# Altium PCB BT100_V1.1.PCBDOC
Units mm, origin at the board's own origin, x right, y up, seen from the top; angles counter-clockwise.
Board outline 126.04 x 85.33 mm, 4 copper layers (Top Layer, GND, POWER, Bottom Layer); 82 components, 62 nets, 257 pads, 145 vias.
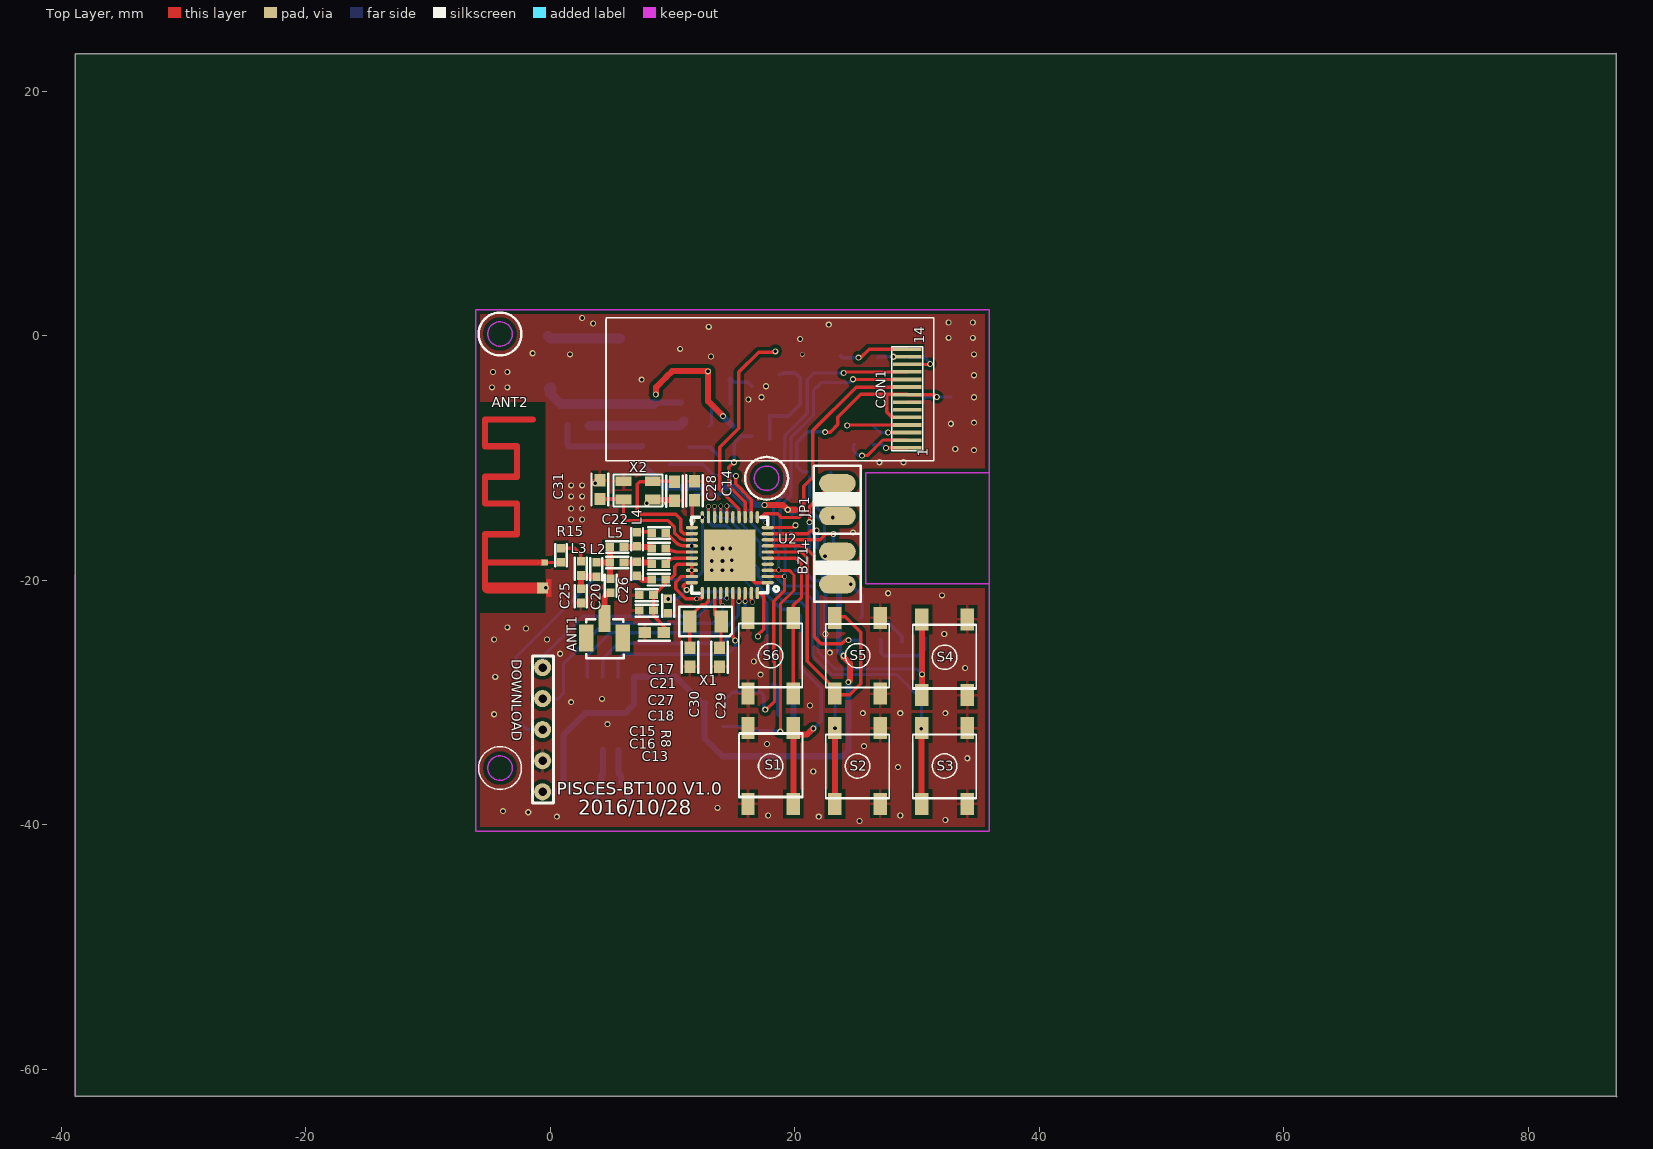
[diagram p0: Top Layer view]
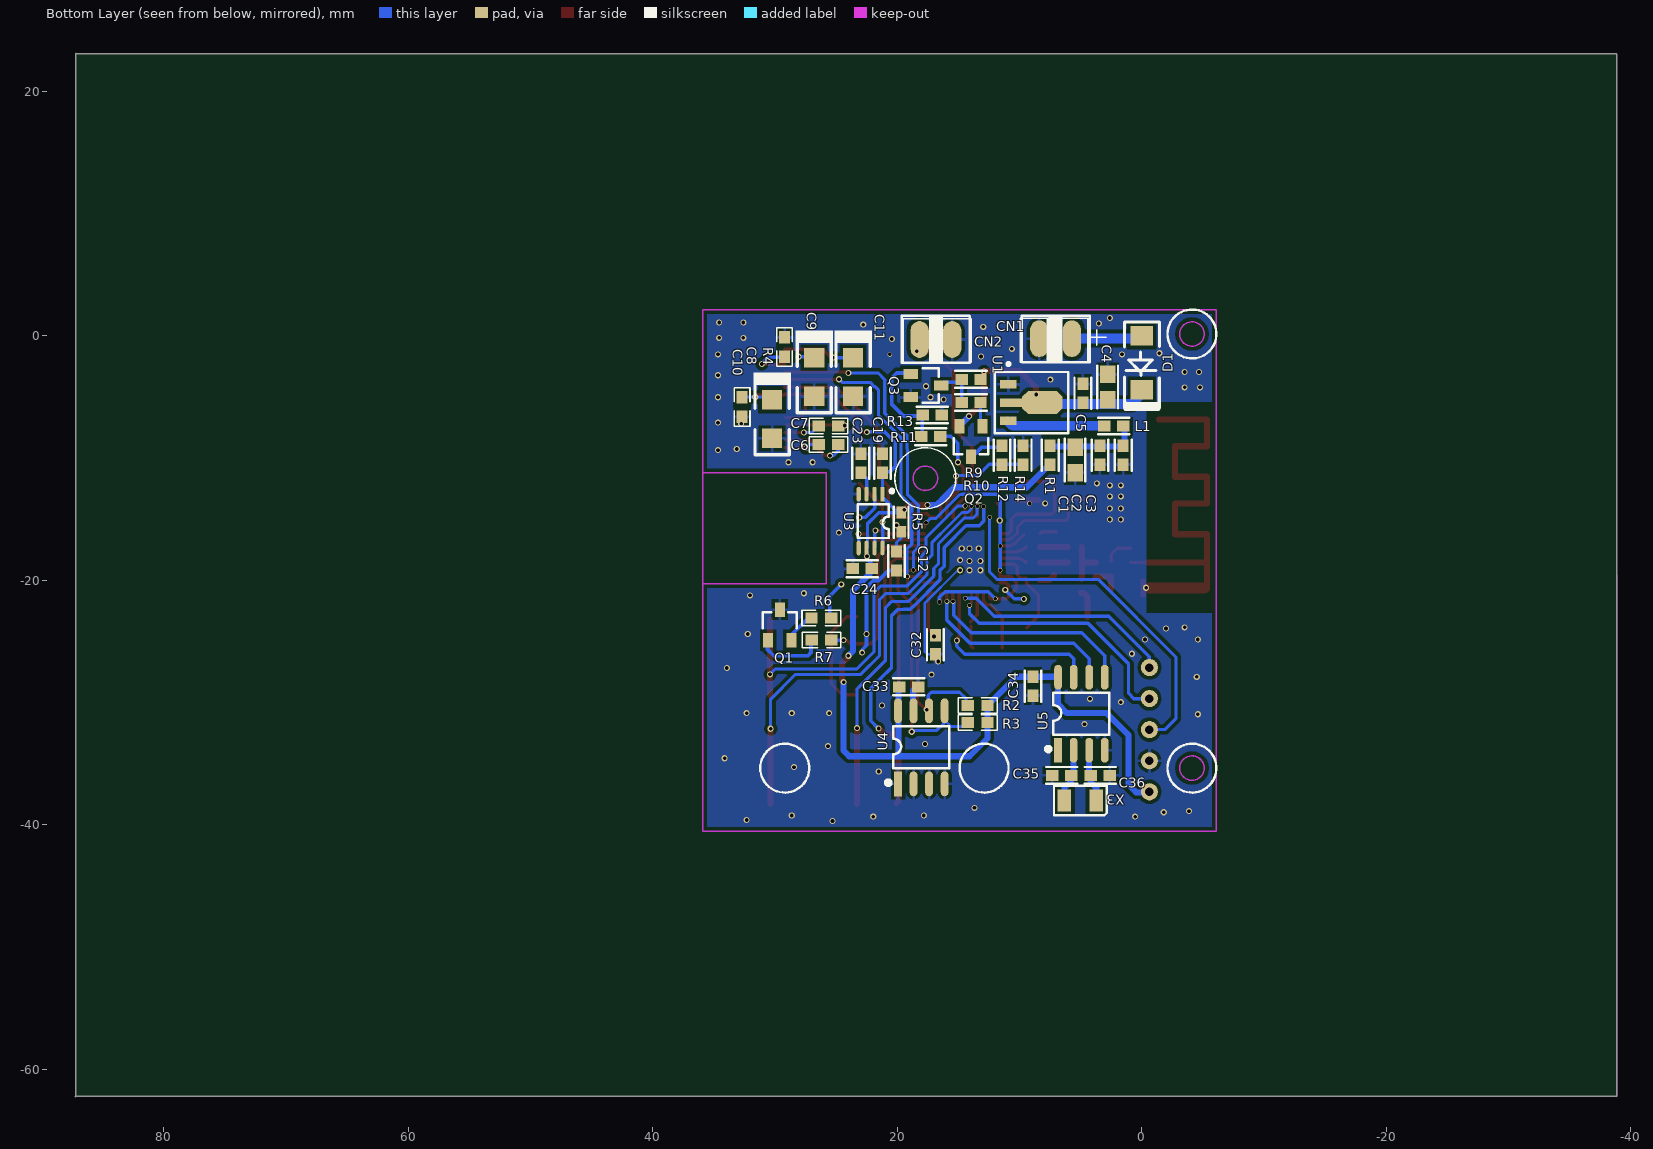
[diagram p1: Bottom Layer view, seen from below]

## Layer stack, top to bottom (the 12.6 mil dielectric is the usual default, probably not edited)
Top Solder: solder mask 0.0102, Solder Resist, Dk 3.5
Top Layer: signal copper 0.0356
Dielectric1: core 0.32, FR-4, Dk 4.8
GND: signal copper 0.0356
Dielectric2: prepreg 0.32, FR-4, Dk 4.8
POWER: signal copper 0.0356
Dielectric3: core 0.32, FR-4, Dk 4.8
Bottom Layer: signal copper 0.0356
Bottom Solder: solder mask 0.0102, Solder Resist, Dk 3.5

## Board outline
-38.826,-62.183 -38.826,23.037 87.104,23.037 87.154,23.087 87.174,23.067 87.174,9.757 87.174,-62.213 87.204,-62.243 87.164,-62.203 -38.836,-62.203

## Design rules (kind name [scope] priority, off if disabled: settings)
Clearance [All] p1: gap=0.1
ComponentClearance [All] p1 off: gap=0.254 collisioncheckmode=3 verticalgap=0.254 showdistances=FALSE
FabricationTestPointUsage TestPointUsage [All] p1: valid=0 allowmultiple=FALSE
FabricationTestpoint Testpoint [(IsPad And (OnTopLayer Or OnBottomLayer))] p1: side=3 testpointundercomponent=TRUE minsize=1.016 maxsize=2.54 preferedsize=1.524 minholesize=0 maxholesize=1.016 preferedholesize=0.813 testpointgrid=0.025 allowsidetop=TRUE allowsidebottom=TRUE usegrid=TRUE gridtolerance=0
Height [All] p1 off: minheight=0 maxheight=25.4 prefheight=12.7
PolygonConnect PolygonConnect_1 [IsVia] p1: connectstyle=Direct reliefconductorwidth=0.254 reliefentries=4 polygonreliefangle="90 Angle" airgapwidth=0.254
PolygonConnect [All] p2: connectstyle=Relief reliefconductorwidth=0.254 reliefentries=4 polygonreliefangle="90 Angle" airgapwidth=0.254
RoutingVias [All] p1: holewidth=0.4 width=0.7 viastyle="Through Hole" minholewidth=0.2 minwidth=0.2 maxholewidth=0.711 maxwidth=1.27
SolderMaskExpansion [All] p1: expansion=0.102
UnpouredPolygon [All] p1: allowunpoured=FALSE
Width [All] p1: maxlimit=1 minlimit=0.2 preferedwidth=0.28 midlayer1_minwidth=0.254 midlayer1_maxwidth=0.254 midlayer1_prefwidth=0.254 midlayer2_minwidth=0.254 midlayer2_maxwidth=0.254 midlayer2_prefwidth=0.254 minimp=50.000000 maximp=50.000000 favimp=50.000000
25 further rules are at their usual default settings.

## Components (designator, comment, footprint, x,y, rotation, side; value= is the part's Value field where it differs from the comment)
ANT1 "ANT" IPEX 4.435,-23.124 r90 top
ANT2 "ANT" ANT -0.45,-18.54 r90 top
BZ1 "BUZZER" 2PAD-9 23.485,-17.663 r270 top
C1 "10uf/10V,0805" PC5-*****-**-0A_0805_TDK 5.451,-10.17 r90 bottom
C2 "0.1uf" PC5-*****-**-0A_0603_TDK 3.419,-9.789 r90 bottom
C3 "2.2uf" PC5-*****-**-0A_0603_TDK 1.514,-9.789 r270 bottom
C4 "10uf/10V,0805" PC5-*****-**-0A_0805_TDK 2.784,-4.201 r270 bottom
C5 "0.1uf" PC5-*****-**-0A_0603_TDK 4.816,-4.709 r270 bottom
C6 "1UF" 0603 26.406,-8.9 r180 bottom
C7 "1UF" 0603 26.406,-7.376 r180 bottom
C8 "4.7UF" 3216C 30.236,-5.217 r90 bottom
C9 "4.7uf" 3216C 26.787,-1.788 r90 bottom
C10 "1uf" 0603 32.664,-5.043 r270 bottom
C11 "4.7uF" 3216C 23.612,-1.788 r90 bottom
C12 "1uf" PC5-*****-**-0A_0603_TDK 20.056,-18.425 r270 bottom
C13 "0.1uf" PC7-*****-KO-0A_0603_TDK 8.499,-24.267 r180 top
C14 "0.1uf" PC5-*****-**-0A_0603_TDK 11.79,-12.69 r90 top
C15 "0.1uf" PC7-*****-KQA0A_0402_YAGEO 7.864,-21.219 r180 top
C16 "0.1uf" PC7-*****-KQA0A_0402_YAGEO 7.864,-22.489 r180 top
C17 "0.1uf" PC7-*****-KQA0A_0402_YAGEO 8.88,-16.139 r180 top
C18 "220pf" PC7-*****-KQA0A_0402_YAGEO 8.88,-19.949 r0 top
C19 "1uf" PC5-*****-**-0A_0603_TDK 21.199,-10.424 r270 bottom
C20 "20P" PC7-*****-KQA0A_0402_YAGEO 4.943,-20.457 r270 top
C21 "18p" PC7-*****-KQA0A_0402_YAGEO 8.88,-17.409 r180 top
C22 "1p" PC7-*****-KQA0A_0402_YAGEO 5.451,-17.282 r180 top
C23 "1uf" PC5-*****-**-0A_0603_TDK 22.977,-10.424 r270 bottom
C24 "0.1uf" PC5-*****-**-0A_0603_TDK 22.85,-19.06 r180 bottom
C25 "1p" PC7-*****-KQA0A_0402_YAGEO 2.504,-21.283 r90 top
C26 "1p" PC7-*****-KQA0A_0402_YAGEO 7.102,-19.06 r270 top
C27 "18p" PC7-*****-KQA0A_0402_YAGEO 8.88,-18.679 r180 top
C28 "27p" PC7-*****-KO-0A_0603_TDK 10.15,-12.71 r90 top
C29 "15P" PC5-*****-**-0A_0603_TDK 13.833,-26.299 r90 top
C30 "15P" PC7-*****-KO-0A_0603_TDK 11.42,-26.299 r90 top
C31 "27p" PC7-*****-KO-0A_0603_TDK 4.054,-12.583 r270 top
C32 "1uf" PC5-*****-**-0A_0603_TDK 16.881,-25.283 r90 bottom
C33 "0.1uf" PC5-*****-**-0A_0603_TDK 19.04,-28.712 r0 bottom
C34 "0.1uf" PC7-*****-KO-0A_0603_TDK 8.894,-28.663 r270 bottom
C35 "15P" PC7-*****-KO-0A_0603_TDK 6.554,-35.953 r0 bottom
C36 "15P" PC7-*****-KO-0A_0603_TDK 3.404,-35.953 r180 bottom
CN1 "CN1" 2PAD-9 5.714,-0.243 r0 bottom
CN2 "CN1" 2PAD-9 18.164,-0.313 r180 bottom
CON1 "FPC-14PIN-F" FFC6214 29.2,-9.154 r90 top locked
D1 "SS12" SS12-DIDEO -0.01,-0.01 r270 bottom
DOWNLOAD "debugger" ISCP-5PIN -0.63,-32.22 r90 top (schematic designator JP2)
JP1 "SIP2" 2PAD-9 23.485,-14.742 r90 top
L1 "BLM18HG102SN1" PC5-*****-**-0A_0603_TDK 2.276,-7.376 r180 bottom
L2 "1nH" PC5-*****-**-0A_0402_TDK 3.764,-19.123 r270 top
L3 "3nH" PC5-*****-**-0A_0402_TDK 2.504,-19.033 r90 top
L4 "2nH" PC5-*****-**-0A_0402_TDK 7.102,-16.647 r270 top
L5 "2nH" PC5-*****-**-0A_0402_TDK 5.451,-18.552 r180 top
Q1 "BC857C" PTR-C0025-00-2A_2SC1623 29.594,-23.653 r180 bottom
Q2 "BC857B" PTR-C0025-00-2A_2SC1623 13.96,-8.646 r0 bottom
Q3 "BC847B" PTR-C0025-00-2A_2SC1623 17.643,-4.074 r270 bottom
R1 "0ohm" PC5-*****-**-0A_0603_TDK 7.483,-9.789 r270 bottom
R2 "4.7K" 0603 14.214,-30.236 r180 bottom
R3 "4.7K" 0603 14.214,-31.633 r180 bottom
R4 "390K" 0603 29.2,-0.137 r270 bottom
R5 "0ohm" PRC-*****-AM-0A_0603 19.675,-15.25 r90 bottom
R6 "10Ω" 0603 26.99,-23.073 r180 bottom
R7 "1K" 0603 25.39,-24.902 r0 bottom
R8 "56k" PRC-*****-BM-0A_0402 9.642,-22.108 r270 top
R9 "47K" PC7-*****-KO-0A_0603_TDK 13.96,-3.566 r180 bottom
R10 "30K" PC5-*****-**-0A_0603_TDK 13.96,-5.471 r180 bottom
R11 "4.7K" PC5-*****-**-0A_0603_TDK 17.262,-8.265 r0 bottom
R12 "75K" PC5-*****-**-0A_0603_TDK 11.42,-9.789 r90 bottom
R13 "100K" PC5-*****-**-0A_0603_TDK 17.135,-6.487 r0 bottom
R14 "30K" PC5-*****-**-0A_0603_TDK 9.694,-9.783 r270 bottom
R15 "0ohm" PC7-*****-KQA0A_0402_YAGEO 0.884,-17.953 r90 top
S1 "SW-PB" TS-030 18.024,-35.189 r270 top
S2 "SW-PB" TS-030 25.136,-35.189 r90 top
S3 "SW-PB" TS-030 32.248,-35.189 r90 top
S4 "SW-PB" TS-030 32.248,-26.299 r90 top
S5 "SW-PB" TS-030 25.136,-26.172 r90 top
S6 "SW-PB" TS-030 18.024,-26.172 r90 top
U1 "HT7333" SOT89 9.515,-5.471 r270 bottom
U2 "CC2541" CC2530_QFN40 17.77,-20.203 r180 top
U3 "PT5102" PT5102 21.199,-12.964 r270 bottom
U4 "AT24C64N" PIC-00570-40-2A_93LC46B 18.024,-33.665 r90 bottom
U5 "DS1302Z" PIC-00570-40-2A_93LC46B 4.934,-30.913 r90 bottom
X1 "32.768KHZ,F=12.5P" FC-135 12.69,-23.378 r180 top
X2 "CY_3225" CY_3225 6.086,-12.329 r0 top
X3 "32.768KHZ,F=6P" FC-135 5.024,-38.023 r0 bottom

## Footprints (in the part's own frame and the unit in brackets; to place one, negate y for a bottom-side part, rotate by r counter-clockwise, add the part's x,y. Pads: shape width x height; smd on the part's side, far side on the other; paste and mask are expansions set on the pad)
2PAD-9 [mm]
  oval 1.5x3 smd: 1(0,0) 2(2.667,0)
  silkscreen extent -1.47,-1.89 4.09,1.92
0603 [mm]
  rect 1x0.9 smd: 1(-0.005,-0.007) 2(1.595,-0.007)
  silkscreen extent -0.79,-0.64 2.38,0.63
3216C [mm]
  rect 1.6x1.65 smd: 1(-0.009,-0.005) 2(-3.184,-0.005)
  silkscreen extent -4.52,-1.54 2.21,1.52
ANT [mm]
  rect 0.5x0.5 smd: 1(0,0)
  rect 0.9x0.9 smd: 2(-2.1,0.2)
  Top Layer lines w0.5: -2.26,4.79 -2.21,4.84 -2.15,4.9 0,4.9 ; 11.7,0.96 11.7,4.9 9.5,4.9 9.5,2.26 7,2.26 7,4.9 4.8,4.9 4.8,2.26 2.3,2.26 2.3,4.9 0,4.9 ; 0,0 0,4.9
  Top Layer lines w0.9: -2.1,4.65 -2.1,0.2
CC2530_QFN40 [mm]
  oval 1x0.28 smd: 1(-0.011,-0.009) 2(-0.011,-0.509) 3(-0.011,-1.009) 4(-0.011,-1.509) 5(-0.011,-2.009) 6(-0.011,-2.509) 7(-0.011,-3.009) 8(-0.011,-3.509) 9(-0.011,-4.009) 10(-0.011,-4.509) 21(6.189,-4.509) 22(6.189,-4.009) 23(6.189,-3.509) 24(6.189,-3.009) 25(6.189,-2.509) 26(6.189,-2.009) 27(6.189,-1.509) 28(6.189,-1.009) 29(6.189,-0.509) 30(6.189,-0.009)
  oval 0.28x1 smd: 11(0.832,-5.359) 12(1.332,-5.359) 13(1.832,-5.359) 14(2.332,-5.359) 15(2.832,-5.359) 16(3.332,-5.359) 17(3.832,-5.359) 18(4.332,-5.359) 19(4.832,-5.359) 20(5.332,-5.359) 31(5.332,0.841) 32(4.832,0.841) 33(4.332,0.841) 34(3.832,0.841) 35(3.332,0.841) 36(2.832,0.841) 37(2.332,0.841) 38(1.832,0.841) 39(1.332,0.841) 40(0.832,0.841)
  rect 4.2x4.2 smd: 41(3.089,-2.259)
  silkscreen extent -0.91,-5.37 6.21,0.85
CY_3225 [mm]
  round 0.5 on Top Overlay: 0(-0.64,-2.06)
  rect 1.3x0.8 smd: 1(-0.095,-1.07) 2(2.293,-1.07) 3(2.293,0.428) 4(-0.095,0.428)
  silkscreen extent -0.91,-1.63 3.11,0.99
FC-135 [mm]
  rect 1.1x1.8 smd: 1(-1.3,0) 2(1.3,0)
  silkscreen extent -2.17,-1.2 2.15,1.19
FFC6214 [mm]
  rect 0.3x2.3 smd: 1(-0.009,0.01) 2(0.611,0.01) 3(1.231,0.01) 4(1.851,0.01) 5(2.471,0.01) 6(3.091,0.01) 7(3.711,0.01) 8(4.331,0.01) 9(4.951,0.01) 10(5.571,0.01) 11(6.191,0.01) 12(6.811,0.01) 13(7.431,0.01) 14(8.051,0.01)
IPEX [mm]
  rect 2.2x1 smd: 1(0,0)
  rect 2.2x1.2 smd: 2(-1.6,-1.5) 3(-1.6,1.49)
  silkscreen extent -3.24,-1.56 -0.05,1.51
ISCP-5PIN [mm]
  round 1.4 hole 0.7: 1(-5.08,0) 2(-2.54,0) 3(0,0) 4(2.54,0) 5(5.08,0)
  silkscreen extent -6.01,-0.89 6.01,0.84
PC5-*****-**-0A_0402_TDK [mm] "0402"
  rect 0.7x0.65 smd: 1(-0.58,0) 2(0.58,0)
  silkscreen extent -0.91,-0.48 0.89,0.48
PC5-*****-**-0A_0603_TDK [mm] "0603"
  rect 1.016x0.9 smd: 1(-0.775,0) 2(0.776,0)
  silkscreen extent -1.28,-0.68 1.28,0.68
PC5-*****-**-0A_0805_TDK [mm] "0805"
  rect 1.424x1.27 smd: 1(-1.04,0) 2(1.04,0)
  silkscreen extent -1.75,-0.84 1.75,0.84
PC7-*****-KO-0A_0603_TDK [mm] "0603"
  rect 1.016x0.9 smd: 1(-0.776,0) 2(0.776,0)
  silkscreen extent -1.28,-0.68 1.28,0.68
PC7-*****-KQA0A_0402_YAGEO [mm] "0402"
  rect 0.7x0.65 smd: 1(-0.58,0) 2(0.58,0)
  silkscreen extent -0.91,-0.48 0.89,0.48
PIC-00570-40-2A_93LC46B [mil] "SOIC-8"
  rect 80x25 smd: 1(-117.5,75)
  oval 80x25 smd: 2(-117.5,25) 3(-117.5,-25) 4(-117.5,-75) 5(117.5,-75) 6(117.5,-25) 7(117.5,25) 8(117.5,75)
  silkscreen extent -119,-90 67,111
PRC-*****-AM-0A_0603 [mm] "0603"
  rect 0.966x0.762 smd: 1(-0.785,0) 2(0.785,0)
  silkscreen extent -1.26,-0.6 1.27,0.6
PRC-*****-BM-0A_0402 [mm] "0402"
  rect 0.7x0.65 smd: 1(-0.58,0) 2(0.58,0)
  silkscreen extent -0.91,-0.48 0.89,0.48
PT5102 [mm]
  rect 1.2x0.35 smd: 1(0,0)
  oval 1.2x0.35 smd: 2(-0.006,-0.65) 3(-0.006,-1.3) 4(-0.006,-1.95) 5(4.4,-1.95) 6(4.4,-1.3) 7(4.4,-0.65) 8(4.4,0)
  silkscreen extent -0.38,-2.03 3.58,0.89
PTR-C0025-00-2A_2SC1623 [mm]
  rect 0.816x1.174 smd: B(-0.95,-1.25) C(0,1.251) E(0.95,-1.25)
  silkscreen extent -1.4,-0.26 1.4,1.04
SOT89 [mm] "SOT-89; Body 4.6 x 4.25 mm, inc. leads (LxW max)"
  oct 1.9x3.3 smd: 0(0,1.388)
  rect 0.7x1.35 smd: 1(-1.5,-1.388) 3(1.5,-1.388)
  rect 0.7x1.8 smd: 2(0,-1.162)
  silkscreen extent -3.27,-2.51 2.5,3.49
SS12-DIDEO [mm]
  rect 1.6x1.8 smd: 1(4.41,-0.01) 2(-0.01,-0.01)
  silkscreen extent -1.14,-1.43 6.03,1.44
TS-030 [mm]
  rect 1.8x1.1 smd: 1(-3.099,1.854) 2(-3.099,-1.854) 3(3.099,-1.854) 4(3.099,1.854)
  silkscreen extent -2.6,-2.6 2.6,2.6

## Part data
BZ1: "Buzzer"
C1 C2 C3 C4 C5 C12 C13 C14 C15 C16 C17 C18 C19 C20 C21 C22 C23 C24 C25 C26 C27 C28 C29 C30 C31 C32 C33 C34 C35 C36: library part PC7_0402_YAGEO, "PC7-*****-KQA0A"
C6 C7: library part "CAP NP_Dup3"
C8 C9 C11: library part CAP_E, "1206"
C10: library part CAP, "Capacitor"
CN1 CN2 JP1: library part CON2, "Connector"
CON1: library part CON14, "Connector"
D1: library part PDD_SD101CWS, "PDD-00330-00-2A"
DOWNLOAD: library part CON5
L1 L2 L3 L4 L5: library part PWL_18nH, "PWL-00195-00-20"
Q1: library part PNP, "PNP Transistor"
Q2: library part PTR-PNP
Q3: library part PTR_2SC3356, "PTR-C0028-00-2A"
R1 R5 R8 R9 R10 R11 R12 R13 R14: library part PRC_0603, "PRC-*****-AM-0A_0603"
R2 R3 R4: library part RES
R6 R7 R15: library part R_Dup3
U1: library part LM117K
U3: library part Component_1_1
U5: library part DS1302
X1: library part CRYSTAL, "Crystal"
X3: library part PTR_16MHZ, "PTR-X0320-20-2A"

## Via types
v1: diameter 0.5, hole 0.3, Top Layer to Bottom Layer, 126 vias
v2: diameter 0.4, hole 0.3, Top Layer to Bottom Layer, 14 vias
v3: diameter 0.35, hole 0.3, Top Layer to Bottom Layer, 4 vias
v4: diameter 0.53, hole 0.3, Top Layer to Bottom Layer, 1 vias

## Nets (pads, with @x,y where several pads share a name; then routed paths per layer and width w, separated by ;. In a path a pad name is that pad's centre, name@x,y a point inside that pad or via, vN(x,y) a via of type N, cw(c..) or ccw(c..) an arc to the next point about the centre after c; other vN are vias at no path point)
AD: R12.1 R14.2 U2.12 | length 9.5
  Top Layer w0.28: v1@15.174,-11.493 15.174,-12.093 15.742,-12.661 15.742,-12.711 ; 15.724,-12.693 16.438,-13.407 U2.12
  Bottom Layer w0.28: R14.2@9.784,-10.503 11.254,-10.503 R12.1@11.264,-10.513 ; R12.1@11.454,-10.503 12.464,-10.503 13.344,-11.383 ; 13.354,-11.383 13.404,-11.433 v1@15.174,-11.433
  other v1: 15.184,-11.473
DC: DOWNLOAD.4 U2.34 | length 20.8
  Top Layer w0.25: U2.34 13.938,-21.901 v2(14.087,-22.05)
  Bottom Layer w0.28: DOWNLOAD.4 0.65,-29.68 1.08,-29.25 1.08,-26.847 4.394,-23.533 13.297,-23.533 14.087,-22.743 v2(14.087,-22.05)
DD: DOWNLOAD.5 U2.35 | length 18
  Bottom Layer w0.28: DOWNLOAD.5 -0.63,-26.27 2.686,-22.954 4.191,-22.954 4.195,-22.95 12.06,-22.95 13.537,-21.473 v3@14.468,-21.473
  other v3: 14.438,-21.473
DJ1: U2.8 U3.5 | length 6.7
  Top Layer w0.28: U2.8 22.065,-16.694 22.538,-16.221 v1(23.149,-16.221)
  Bottom Layer w0.28: U3.5 v1(23.149,-16.221)
DJ2: U2.9 U3.7 | length 5.6
  Top Layer w0.28: U2.9 21.066,-16.194 21.33,-15.93 v1(21.78,-15.93)
  Bottom Layer w0.28: v1(21.78,-15.93) 21.849,-15.999 U3.7
GND: C1.1 C2.1 C3.2 C4.1 C5.1 C8.2 C9.2 C10.2 C11.2 C12.2 C13.2 C14.2 C15.2 C16.2 C17.2 C18.1 C19.1 C23.1 C24.1 C25.1 C26.2 C28.1 C29.1 C30.1 C31.1 C32.1 C33.1 C34.2 C35.2 C36.2 CN1.2 CN2.2 CON1.7 DOWNLOAD.2 L4.1 Q1.C Q3.E R4.1 R8.2 R13.1 R14.1 S1.2 S1.3 S2.2 S2.3 S3.2 S3.3 S4.2 S4.3 S5.2 S5.3 S6.1 S6.4 U1.1 U2.1 U2.41 U3.4 U4.1 U4.2 U4.3 U4.4 U4.7 U5.4 X2.2 X2.4 | length 26.1
  Top Layer w0.2: U2.1@17.731,-20.266 U2.1@17.804,-20.193
  Top Layer w0.28: U2.41@16.373,-19.822 16.745,-20.194 U2.1
  Top Layer w0.3: L4.1@7.015,-16.023 8.147,-16.023 C17.2@8.278,-16.155
  Top Layer w0.5: C26.2@7.174,-19.593 7.574,-19.993 C18.1@8.364,-19.993 ; X2.2@8.434,-13.443 C28.1@10.244,-13.443
  Bottom Layer w0.2: v1(14.849,-19.187) 15.047,-19.187 17.73,-21.87 17.73,-25.842 17.513,-26.058 C32.1
  Bottom Layer w0.3: C12.2 20.705,-19.201 21.534,-20.03 21.955,-20.03 22.509,-20.584 22.509,-25.323 22.86,-25.674 v1(22.86,-25.92)
  Bottom Layer w0.5: C33.1@18.254,-28.563 18.694,-29.003 U4.7@18.694,-30.943
  other v1: 25.29,-39.69 32.31,-39.6 0.54,-39.33 21.96,-39.33 17.82,-39.24 28.62,-39.24 -1.8,-38.97 -3.87,-38.88 13.68,-38.61 21.51,-35.64 28.44,-35.28 34.11,-34.56 25.65,-33.57 17.73,-33.39 4.68,-31.77 -4.59,-30.96 25.56,-30.87 28.62,-30.87 32.31,-30.87 21.24,-30.24 1.71,-29.97 4.23,-29.7 -4.5,-27.9 17.19,-27.72 33.93,-27.18 16.65,-26.64 0.81,-26.01 -4.59,-24.84 -0.27,-24.84 22.509,-24.394 32.22,-24.39 -1.98,-23.94 -3.51,-23.85 32.04,-21.24 27.63,-21.06 -0.36,-20.61 13.198,-19.187 14.087,-19.187 13.198,-18.425 14.087,-18.425 14.85,-18.36 13.325,-17.409 14.087,-17.409 14.722,-17.409 24.75,-16.11 1.71,-15.03 2.61,-15.03 1.71,-14.13 2.61,-14.13 7.904,-13.713 1.71,-13.14 2.61,-13.14 1.71,-12.24 2.61,-12.24 3.673,-12.075 26.91,-10.35 28.89,-10.35 34.65,-9.36 33.12,-9.27 32.76,-7.2 34.65,-7.11 16.2,-5.22 17.28,-5.04 34.65,-5.04 -4.77,-4.23 -3.51,-4.23 17.64,-4.14 7.47,-3.6 34.65,-3.24 -4.68,-2.97 -3.51,-2.97 13.14,-1.71 1.62,-1.53 34.65,-1.53 -1.44,-1.44 10.62,-1.08 20.43,-0.27 32.58,-0.18 34.56,-0.18 12.96,0.72 22.77,0.9 3.51,0.99 32.58,1.08 34.56,1.08 2.61,1.44
  other v2: 9.164,-13.723 20.61,-1.53
LCDRES: CON1.9 U2.11 | length 20.4
  Top Layer w0.28: U2.11 17.286,-14.844 17.55,-14.58 18.611,-14.58 18.9,-14.869 20.31,-14.869 20.719,-14.46 20.719,-12.301 21.453,-11.567 21.453,-7.757 25.007,-4.203 CON1.9
MODE-SW: CN2.1 U2.14 | length 16.8
  Top Layer w0.28: 14.85,-13.579 15.424,-14.153 U2.14@15.424,-14.833 ; 14.854,-13.575 13.86,-12.582 13.86,-9.127 15.414,-7.573 ; 15.424,-7.573 15.424,-2.973 17.044,-1.353 ; U2.14 U2.14@15.438,-14.833 ; 17.054,-1.363 18.374,-1.363 v1@18.414,-1.323
  other v1: 18.405,-1.28
NetANT1_1: ANT1.1 C20.2 | length 2.2
  Top Layer w0.5: ANT1.1@4.435,-22.997 4.435,-21.545 cw(c4.943,-21.545) C20.2
NetANT2_1: ANT2.1 R15.1 | length 1.3
  Top Layer w0.28: ANT2.1@-0.391,-18.552 0.865,-18.552 R15.1
NetBZ1_2: BZ1.2 R6.2 | length 3.2
  Bottom Layer w0.3: v1(24.57,-20.34) 25.517,-21.287 25.517,-22.959 R6.2
NetC1_2: C1.2 C2.2 C3.1 L1.2 R1.1 | length 7.8
  Bottom Layer w0.5: L1.2@1.404,-7.343 1.404,-8.933 1.544,-9.073 7.454,-9.073 R1.1@7.504,-9.023
NetC6_1: C6.1 CON1.1 | length 2.9
  Top Layer w0.254: v1(27.45,-9.18) 27.467,-9.163 CON1.1
  Bottom Layer w0.254: C6.1 C6.1@26.44,-8.907 ; C6.1@26.414,-8.933 C6.1@26.44,-8.907 ; v1(27.45,-9.18) 27.177,-8.907 C6.1@26.44,-8.907
NetC6_2: C6.2 CON1.2 | length 5.7
  Top Layer w0.254: v1@25.413,-9.81 v1(25.486,-9.81) 25.92,-9.81 27.197,-8.533 CON1.2@29.154,-8.533
  Bottom Layer w0.254: C6.2 C6.2@24.811,-8.986 ; C6.2@24.874,-8.923 C6.2@24.811,-8.986 ; v1(25.486,-9.81) 25.2,-9.81 24.811,-9.421 C6.2@24.811,-8.986
NetC7_1: C7.1 CON1.3 | length 3.1
  Top Layer w0.254: v1(27.63,-7.92) 29.187,-7.92 CON1.3
  Bottom Layer w0.254: C7.1@26.374,-7.323 26.364,-7.323 26.961,-7.92 v1(27.63,-7.92)
NetC7_2: C7.2 CON1.4 | length 4.9
  Top Layer w0.254: v1@24.194,-7.293 24.204,-7.303 CON1.4@29.054,-7.303
  other v1: 24.274,-7.343
NetC9_1: C9.1 CON1.13 | length 1.3
  Bottom Layer w0.3: C9.1 26.856,-1.723 v1(28.057,-1.723)
NetC11_1: C11.1 CON1.14 | length 5.8
  Top Layer w0.3: v1(25.2,-1.8) 25.378,-1.8 26.075,-1.103 CON1.14
  Bottom Layer w0.3: C11.1@23.714,-1.673 23.726,-1.661 23.865,-1.8 v1(25.2,-1.8)
NetC12_1: C12.1 C13.1 C14.1 C15.1 C16.1 C17.1 C18.2 R5.1 U2.10 U2.21 U2.24 U2.27 U2.28 U2.29 U2.31 U2.39 | length 41.8
  Top Layer w0.25: v2(17.64,-15.3) 17.781,-15.441 U2.10 19.866,-15.694 v1(20.056,-15.504)
  Top Layer w0.28: C18.2@9.388,-20.076 9.388,-20.275 C15.1 8.444,-22.919 C13.1@9.411,-23.886 ; C18.2@9.46,-19.822 9.896,-19.822 10.17,-19.548 10.17,-18.9 10.376,-18.694 U2.27 U2.29 10.726,-19.694 10.26,-20.16 10.26,-20.694 11.076,-21.51 v2(11.97,-21.51) 12.33,-21.51 12.438,-21.402 U2.31 ; C17.1@9.642,-16.266 10.277,-16.901 ccw(c10.983,-16.195) 10.983,-17.194 v3(11.581,-17.194) ; U2.21 11.581,-15.149 v1(11.61,-15.12) 11.61,-13.944 11.581,-13.915 C14.1@11.801,-13.695 ; U2.39 16.438,-21.727 16.491,-21.78 16.497,-21.773 v2(16.544,-21.773)
  Bottom Layer w0.25: 14.67,-12.983 14.873,-12.983 16.83,-14.94 17.28,-14.94 v2(17.64,-15.3) ; R5.1 19.675,-16.525 20.056,-16.906 C12.1
  Bottom Layer w0.28: v3(11.581,-19.194) 11.581,-13.259 11.857,-12.983 14.67,-12.983 ; v2(11.97,-21.51) 12.547,-20.933 16.073,-20.933 16.544,-21.404 v2(16.544,-21.773)
NetC20_1: C20.1 C22.2 L2.1 L5.2 | length 3.7
  Top Layer w0.5: L2.1 3.773,-18.552 L5.2 ; C22.2 L5.2 ; C20.1 cw(c4.943,-19.805) 4.871,-19.805 L5.2
NetC21_1: C21.1 U2.25 | length 2.2
  Top Layer w0.28: C21.1@9.46,-17.282 ccw(c10.454,-16.288) 10.454,-17.694 U2.25
NetC21_2: C21.2 C22.1 L4.2 | length 2.3
  Top Layer w0.5: C22.1 C21.2@8.3,-17.282
NetC23_2: C23.2 U3.3 | length 2.1
  Bottom Layer w0.28: U3.3@22.469,-12.988 U3.3 ; U3.3@22.484,-13.033 22.484,-11.663 C23.2@22.944,-11.203
NetC25_2: C25.2 L2.2 L3.1 | length 2.3
  Top Layer w0.5: C25.2 2.504,-19.703 L2.2
NetC26_1: C26.1 C27.2 L5.1 | length 2.3
  Top Layer w0.5: L5.1 C27.2@8.3,-18.552
NetC27_1: C27.1 U2.26 | length 2.2
  Top Layer w0.28: C27.1@9.46,-18.552 cw(c10.325,-19.417) 10.325,-18.194 U2.26
NetC28_2: C28.2 U2.22 X2.3 | length 11.7
  Top Layer w0.28: X2.3@8.038,-11.901 10.116,-11.901 C28.2 ; X2.3 8.332,-11.948 7.31,-11.948 7.102,-12.156 7.102,-14.361 7.356,-14.615 10.277,-14.615 10.658,-14.996 10.658,-15.967 ; 10.773,-16.082 10.658,-15.967 ; U2.22 10.931,-16.194 10.704,-15.967 10.658,-15.967
NetC29_2: C29.2 U2.33 X1.1 | length 4.4
  Top Layer w0.28: U2.33 13.438,-22.826 X1.1 ; C29.2 13.96,-25.396 X1.1@13.96,-23.759
NetC30_2: C30.2 U2.32 X1.2 | length 5
  Top Layer w0.28: X1.2 11.39,-22.99 12.39,-21.99 12.681,-21.99 12.938,-21.733 U2.32 ; C30.2 X1.2@11.42,-23.632
NetC31_2: C31.2 U2.23 X2.1 | length 9.9
  Top Layer w0.25: X2.1@5.991,-13.414 5.991,-14.901 6.213,-15.123 9.642,-15.123 10.15,-15.631 10.15,-16.116 10.562,-16.529
  Top Layer w0.28: X2.1@5.991,-13.414 X2.1 ; 10.573,-16.518 ccw(c10.997,-16.095) 10.997,-16.694 U2.23
  Top Layer w0.3: C31.2 X2.1@5.818,-13.359
NetC32_2: C32.2 U2.40 | length 4.3
  Top Layer w0.28: U2.40 17.174,-21.044 17.46,-21.33 17.46,-23.997 v1@16.944,-24.513
  Bottom Layer w0.28: C32.2 16.938,-24.451 v1(16.994,-24.603)
NetC35_1: C35.1 U5.2 X3.2 | length 4.4
  Bottom Layer w0.5: U5.2 5.569,-35.743 C35.1 5.779,-36.437 6.324,-36.983 X3.2
NetC36_1: C36.1 U5.3 X3.1 | length 4.4
  Bottom Layer w0.5: X3.1 3.724,-36.983 4.179,-36.528 C36.1 4.299,-35.833 U5.3
NetCN1_1: CN1.1 D1.2 | length 6
  Bottom Layer w0.8: D1.2@-0.196,-0.033 0.014,-0.243 CN1.1
NetCON1_12: CON1.12 R4.2 | length 3.9
  Top Layer w0.254: CON1.12 v1@31.025,-2.343
  Bottom Layer w0.254: R4.2@29.244,-1.763 30.584,-1.763 v1@31.124,-2.303
  other v1: 31.064,-2.313
NetL1_1: L1.1 U1.3 | length 7.9
  Bottom Layer w0.8: L1.1@3.184,-7.373 10.554,-7.373 U1.3@10.924,-7.003
NetL3_2: L3.2 R15.2 | length 2.4
  Top Layer w0.28: R15.2 2.014,-17.373 2.504,-17.863 L3.2
NetQ1_B: Q1.B R7.2 | length 5.9
  Bottom Layer w0.3: R7.2 27.041,-24.951 27.041,-25.918 27.295,-26.172 30.089,-26.172 30.597,-25.664 30.597,-24.816 Q1.B@30.658,-24.755
NetQ1_E: Q1.E R6.1 | length 2.7
  Bottom Layer w0.3: R6.1@27.168,-22.997 28.758,-24.587 Q1.E@28.758,-25.009
NetQ2_B: Q2.B R10.2 | length 2.1
  Bottom Layer w0.25: Q2.B@12.984,-7.443 13.174,-7.253 R10.2@13.174,-5.393
NetQ2_C: Q2.C R12.2 | length 2.8
  Bottom Layer w0.3: R12.2@11.364,-9.113 13.064,-9.113 Q2.C@13.834,-9.883
NetQ3_B: Q3.B R11.2 R13.2 | length 8.7
  Bottom Layer w0.3: R11.2@17.954,-8.483 17.954,-6.623 17.904,-6.573 19.474,-6.573 20.454,-5.593 20.454,-3.483 20.024,-3.053 19.054,-3.053 Q3.B@19.004,-3.103 ; Q3.B@18.744,-3.153 Q3.B@18.764,-3.173
NetQ3_C: Q3.C R9.1 R10.1 | length 3.7
  Bottom Layer w0.3: R10.1@14.694,-5.543 14.724,-5.513 R9.1@14.724,-3.463 ; R9.1@15.134,-3.803 16.174,-3.803 Q3.C@16.484,-4.113
  Bottom Layer w0.5: R9.1@14.744,-3.633 R9.1@14.804,-3.693
NetR8_1: R8.1 U2.30 | length 3.1
  Top Layer w0.28: v1(11.16,-20.79) 10.89,-20.52 10.89,-20.43 11.126,-20.194 U2.30
  Bottom Layer w0.28: v1(9.642,-21.528) 10.432,-21.528 11.16,-20.8 v1(11.16,-20.79)
O1: JP1.1 U3.2 | length 2.6
  Bottom Layer w0.28: U3.2@21.834,-13.091 21.834,-14.107 22.596,-14.869 v4(23.104,-14.869)
O2: JP1.2 U3.8 | length 6.1
  Top Layer w0.28: v1(21.199,-15.25) 21.199,-13.98 JP1.2@23.104,-12.075
  Bottom Layer w0.28: U3.8 21.19,-17.355 21.19,-15.259 v1(21.199,-15.25)
P10: R11.1 U2.13 | length 8.4
  Top Layer w0.28: v1(15.03,-10.35) 14.609,-10.771 14.609,-11.199 14.594,-11.214 14.594,-12.273 15.944,-13.623 U2.13@15.944,-14.833 ; U2.13 U2.13@15.938,-14.833
  Bottom Layer w0.28: v1(15.03,-10.35) 15.03,-8.807 15.604,-8.233 R11.1@16.464,-8.233
RST: DOWNLOAD.3 U2.20 | length 30.2
  Bottom Layer w0.25: DOWNLOAD.3 -1.89,-32.22 -2.79,-31.32 -2.79,-26.28 3.563,-19.927 11.843,-19.927 12.438,-19.332 v3(12.438,-14.844) v3(12.438,-14.844)
S1: S1.1 S1.4 U2.19 | length 32
  Top Layer w0.25: U2.19 12.938,-13.989 v2@12.944,-13.983
  Top Layer w0.28: v2@12.944,-13.983 v2@12.954,-13.973
  Top Layer w0.5: S1.1@19.878,-31.963 19.878,-38.059 S1.4@20.056,-38.237 ; S1.1@20.204,-32.623 20.984,-32.623 v1@21.464,-32.143
  Bottom Layer w0.28: v2@12.904,-13.993 12.916,-14.005 12.916,-15.155 13.294,-15.533 14.374,-15.533 15.204,-16.363 ; 15.23,-16.393 16.159,-17.322 16.159,-18.846 16.5,-19.187 16.5,-19.962 18.652,-22.115 ; 18.666,-22.115 18.913,-22.362 ; 18.924,-22.353 18.954,-22.383 19.484,-22.383 ; 19.494,-22.393 19.954,-22.393 20.464,-22.903 20.464,-27.163 21.327,-28.026 ; 21.344,-28.043 21.327,-28.026 ; v1@21.584,-32.083 22.164,-31.503 22.164,-28.853 21.337,-28.026 21.327,-28.026
  other v1: 21.518,-32.119
  other v2: 12.938,-13.973
S2: S2.1 S2.4 U2.18 | length 30.5
  Top Layer w0.25: v2@13.424,-13.943 13.438,-13.957 U2.18
  Top Layer w0.5: S2.1 v1(23.282,-32.09)
  Bottom Layer w0.25: v2@13.464,-13.973 13.454,-13.973 13.454,-14.583 13.784,-14.913 14.509,-14.913 16.624,-17.028 16.624,-18.654 17.008,-19.037 17.008,-19.664 19.056,-21.711 ; 19.056,-21.727 20.437,-21.727 20.945,-22.235 20.945,-26.553 23.104,-28.712
  Bottom Layer w0.254: 23.104,-28.712 23.282,-28.89 v1(23.282,-32.09)
  other v2: 13.438,-13.953
S3: S3.1 S3.4 U2.17 | length 36.6
  Top Layer w0.25: v2@13.934,-13.943 13.938,-13.947 U2.17
  Top Layer w0.5: S3.1@30.343,-38.288 v1(30.343,-32.141) S3.4
  Bottom Layer w0.25: v2@13.914,-13.983 13.914,-14.143 14.234,-14.463 14.704,-14.463 15.684,-15.443 ; 15.68,-15.447 17.134,-16.901 17.134,-17.916 17.574,-18.356 17.574,-19.568 19.098,-21.092 20.945,-21.092 21.444,-21.591 21.444,-26.163 22.977,-27.696 28.311,-27.696
  Bottom Layer w0.254: 28.311,-27.698 30.343,-29.73 v1(30.343,-32.141)
  other v2: 13.938,-13.933
S4: S4.1 S4.4 U2.16 | length 33
  Top Layer w0.25: v2@14.424,-13.923 14.438,-13.937 U2.16
  Top Layer w0.5: S4.1 S4.4
  Bottom Layer w0.25: v2@14.454,-13.943 15.074,-13.943 16.014,-14.883 ; 16.01,-14.887 17.643,-16.52 17.643,-17.663 18.024,-18.044 18.024,-19.315 19.166,-20.457 21.326,-20.457 21.894,-21.025 21.894,-25.851 23.289,-27.246 29.944,-27.246 v1(30.394,-27.696)
  other v2: 14.438,-13.923
S5: S5.1 S5.4 U2.6 | length 24.4
  Top Layer w0.28: U2.6 20.551,-17.694 21.028,-18.171 21.028,-26.636 S5.1@23.358,-28.966 ; S5.4@23.282,-22.997 24.127,-22.997 25.39,-24.26 25.39,-28.458 24.501,-29.347 S5.1@23.358,-29.347
S6: S6.2 S6.3 U2.5 | length 13.8
  Top Layer w0.28: U2.5 20.079,-18.194 20.548,-18.663 20.548,-21.392 19.878,-22.062 S6.3 S6.2
SCL: CON1.10 R2.1 U2.2 U4.6 | length 42.7
  Top Layer w0.25: 18.278,-26.68 18.278,-21.727
  Top Layer w0.254: v1@17.594,-30.633 18.344,-29.883 18.344,-26.663 ; U2.2 v2@19.166,-19.694 ; 18.274,-21.723 19.166,-20.831 v2@19.166,-19.694 ; v2(19.167,-19.695) v2@19.166,-19.694 ; v1(24.75,-3.566) 24.767,-3.583 CON1.10
  Bottom Layer w0.254: R2.1@14.364,-30.283 14.364,-29.703 14.904,-29.163 17.204,-29.163 17.454,-29.413 17.454,-30.453 U4.6@17.434,-30.473 ; v2(19.167,-19.695) 19.211,-19.651 19.211,-17.846 19.208,-17.843 19.208,-17.45 18.81,-17.052 18.81,-13.963 19.675,-13.098 19.675,-8.342 21.534,-6.483 21.534,-4.433 21.794,-4.173 ; 21.828,-4.207 22.215,-3.82 24.496,-3.82 v1(24.75,-3.566)
  other v1: 17.584,-30.583
SDA: CON1.11 R3.1 U2.3 U4.5 | length 46.5
  Top Layer w0.25: U2.3 19.555,-19.194 ; v1@18.82,-32.361 18.82,-21.947
  Top Layer w0.254: 18.82,-21.947 19.929,-20.838 19.929,-19.568 19.555,-19.194 ; v1(23.993,-3.058) 24.088,-2.963 CON1.11
  Bottom Layer w0.254: R3.1@14.104,-31.963 15.594,-31.963 U4.5@16.284,-31.273 ; U4.5@16.134,-31.353 16.134,-31.643 16.794,-32.303 18.784,-32.303 v1@18.854,-32.373 ; v2@18.659,-19.067 18.659,-17.694 18.27,-17.305 18.27,-13.861 19.167,-12.964 19.167,-9.283 ; 19.184,-9.283 19.184,-8.173 21.014,-6.343 21.014,-3.593 21.549,-3.058 v1(23.993,-3.058)
  other v1: 18.804,-32.393
  other v2: 18.684,-19.163
SPK_PD0: R7.1 U2.7 | length 14.9
  Top Layer w0.28: U2.7 20.73,-17.194 21.58,-18.044 21.58,-24.64 22.14,-25.2 23.815,-25.2 24.12,-24.895 v1(24.39,-24.895)
  Bottom Layer w0.28: v1(24.39,-24.895) R7.1
T-CE: U2.37 U5.5 | length 17.3
  Top Layer w0.28: v2(15.438,-21.727) U2.37
  Bottom Layer w0.28: U5.5 3.029,-26.158 4.894,-24.293 13.934,-24.293 15.357,-22.87 15.357,-21.808 v2(15.438,-21.727)
T-I/O: U2.38 U5.6 | length 16.7
  Top Layer w0.28: v2(15.938,-21.727) U2.38
  Bottom Layer w0.28: U5.6 4.299,-26.418 5.564,-25.153 14.046,-25.153 15.948,-23.251 15.938,-23.24 v2(15.938,-21.727)
T-SCLK: U2.36 U5.7 | length 15.9
  Top Layer w0.28: U2.36 14.938,-24.61 15.12,-24.792 v1(15.12,-24.93)
  Bottom Layer w0.28: U5.7 5.569,-26.408 5.924,-26.053 14.474,-26.053 15.12,-25.407 v1(15.12,-24.93)
VCC: BZ1.1 C8.1 C10.1 C19.2 C24.2 C33.2 C34.1 CON1.5 CON1.8 DOWNLOAD.1 R1.2 R2.2 R3.2 R5.2 U3.1 U3.6 U4.8 U5.8 | length 105.9
  Top Layer w0.28: v1(22.474,-7.893) 22.887,-7.893 23.517,-7.263 23.517,-6.66 25.374,-4.803 27.524,-4.803 ; CON1.5@29.164,-6.693 27.974,-6.693 27.524,-6.243 27.524,-4.803 ; CON1.8@29.19,-4.803 27.524,-4.803 ; CON1.8@29.204,-4.843 31.424,-4.843 v1@31.564,-4.983
  Top Layer w0.5: v1(17.524,-13.843) 19.03,-13.843 v1(19.421,-14.234) 20.056,-14.234 ; v1(23.993,-26.172) 23.993,-26.299 24.501,-26.807 24.501,-28.204 v1(24.374,-28.331)
  Bottom Layer w0.28: R5.2 R5.2@19.952,-14.465 ; R5.2@19.802,-14.615 R5.2@19.952,-14.465 ; 20.954,-7.943 20.142,-8.755 20.142,-10.701 20.584,-11.143 C19.2@21.034,-11.143 ; 21.014,-7.883 21.014,-7.873 v1@22.354,-7.873 ; C19.2@21.199,-11.567 21.199,-13.218 R5.2@19.952,-14.465 ; C24.2@21.693,-19.06 22.469,-18.284 U3.6@22.469,-17.536 ; U3.6 22.425,-17.29 22.425,-15.377 21.513,-14.465 R5.2@19.952,-14.465 ; C8.1@30.524,-5.173 30.684,-5.013 C10.1@32.814,-5.013
  Bottom Layer w0.5: DOWNLOAD.1@-0.63,-37.35 0.45,-37.35 1.08,-36.72 1.08,-32.67 2.88,-30.87 6.12,-30.87 6.839,-30.151 U5.8 ; U5.8@6.88,-27.888 C34.1 10.264,-27.888 R2.2@12.557,-30.18 ; R1.2@7.564,-10.683 ccw(c7.484,-10.683) 7.484,-10.603 ccw(c7.554,-10.603) 7.554,-10.673 R1.2@7.634,-10.673 ; R1.2@7.594,-10.583 9.474,-12.463 ; 9.544,-12.393 15.324,-12.393 16.377,-13.446 ; R2.2@12.564,-30.143 R2.2@12.579,-30.158 ; R2.2 R2.2@12.614,-30.238 ; R2.2@12.704,-30.033 R2.2@12.579,-30.158 ; 16.294,-13.363 16.774,-13.843 v1@17.494,-13.843 ; C33.2@19.894,-28.493 19.894,-34.363 19.924,-34.393 ; C24.2@22.215,-19.06 22.215,-19.441 23.612,-20.838 23.612,-25.791 v1(23.993,-26.172) ; v1@24.404,-28.383 24.404,-33.916 23.927,-34.393 14.084,-34.393 12.614,-32.923 R2.2@12.614,-30.238 ; R2.2@12.557,-30.18 R2.2@12.579,-30.158 ; R2.2@12.557,-30.18 R2.2@12.614,-30.238 ; R2.2@12.579,-30.158 12.614,-30.193 R2.2@12.614,-30.238
  other v1: 22.469,-18.044 31.604,-5.013
VDD: C4.2 C5.2 D1.1 Q2.E R9.2 U1.0 U1.2 | length 22.2
  Top Layer w0.5: v1@8.654,-4.773 8.654,-4.223 9.414,-3.463 ; 9.484,-3.373 9.964,-2.893 v1@12.874,-2.893 ; v1@12.914,-2.885 12.914,-5.363 v1(14.13,-6.579)
  Bottom Layer w0.5: U1.0@8.034,-5.623 8.186,-5.471 U1.2 ; v1(14.13,-6.579) 14.13,-6.616 Q2.E
  Bottom Layer w0.8: D1.1@-0.016,-4.733 0.844,-5.593 U1.0@8.504,-5.593
  Bottom Layer w1: D1.1@-0.006,-4.323 D1.1@0.024,-4.323
  other v1: 8.634,-4.813 12.894,-2.923
pads on no net: ANT1.2 ANT1.3 ANT2.2 CON1.6 U2.4 U2.15 U5.1 X2.0

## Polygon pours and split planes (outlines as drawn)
GND on Bottom Layer "01 Bottom Layer-No Net" (solid, remove dead copper, pour order 38): -7.02,-22.68 -7.11,-22.68 -0.36,-22.68 -0.36,-5.4 -6.57,-5.4 -6.84,-5.13 -7.02,-4.95 -7.02,2.97 42.39,2.97 46.62,7.2 44.73,5.31 44.73,-47.07 7.02,-47.07 3.78,-50.31 -7.65,-38.88 -14.4,-38.88 -14.4,-36.18 -9.81,-31.59
GND on Top Layer "01 Bottom Layer-No Net" (solid, remove dead copper, pour order 40): -6.93,-22.68 -0.36,-22.68 -0.36,-5.4 -9.09,-5.4 -8.19,-4.5 -8.19,4.68 47.61,4.68 47.79,4.5 44.46,1.17 44.46,-51.57 18.45,-51.57 15.12,-48.24 -12.6,-48.24 -12.6,-32.04 -16.29,-28.35

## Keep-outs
Keep-Out Layer:
  circle w0.127: c-4.106,0.137 r1
  circle w0.127: c17.694,-11.663 r1
  circle w0.127: c-4.106,-35.363 r1
  lines w0.127: -38.826,-62.223 -38.826,-19.563 ; -6.106,-40.513 35.894,-40.513 ; 35.884,-11.205 25.805,-11.205 25.805,-20.275 35.894,-20.275 35.894,-40.523 ; 35.894,-11.205 35.894,2.137 ; 35.894,-40.523 -6.106,-40.523 -6.106,2.137 35.894,2.137 ; 35.894,-40.523 35.894,2.137

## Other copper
Top Layer:
  rectangle net GND: -0.36,-21.39 0.1,-19.89

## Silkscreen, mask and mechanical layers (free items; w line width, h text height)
Top Overlay:
  circle w0.2: c17.694,-11.663 r1.75
  circle w0.2: c-4.106,0.137 r1.75
  circle w0.127: c-4.106,-35.363 r1.75
  rectangle: 21.545,-19.525 25.36,-18.395
  rectangle: 21.595,-13.935 25.36,-12.765
  lines w0.013: 4.558,1.312 4.558,-10.188 31.158,-10.188
  lines w0.127: 21.55,-10.616 21.55,-21.709 21.545,-21.714 25.345,-21.714 25.345,-10.631 ; 4.553,-10.221 4.562,-10.212 4.562,1.438 4.603,1.479 31.353,1.479 31.353,-10.221 4.553,-10.221 ; 15.422,-28.719 15.422,-23.519 20.622,-23.519 20.622,-28.719 15.422,-28.719 ; 15.442,-37.66 15.442,-32.46 20.642,-32.46 20.642,-37.66 15.442,-37.66 ; 22.534,-37.85 22.534,-32.65 27.734,-32.65 27.734,-37.85 22.534,-37.85 ; 22.534,-28.807 22.534,-23.607 27.734,-23.607 27.734,-28.807 22.534,-28.807 ; 27.93,-9.408 30.47,-9.408 30.47,-0.899 27.93,-0.899 27.93,-9.408 ; 29.646,-37.85 29.646,-32.65 34.846,-32.65 34.846,-37.85 29.646,-37.85 ; 29.646,-28.807 29.646,-23.607 34.846,-23.607 34.846,-28.807 29.646,-28.807
  text "+" at 21.222,-17.552 h0.8 r90
  text "PISCES-BT100 V1.0" at 0.514,-37.543 h1
  text "2016/10/28" at 2.304,-39.173 h1.2
Bottom Overlay:
  circle w0.2: c29.194,-35.363 r2
  circle w0.2: c-4.106,0.137 r2
  circle w0.2: c-4.106,-35.363 r2
  circle w0.2: c12.894,-35.363 r2
  circle w0.127: c17.694,-11.663 r2.5
  rectangle: 16.235,-2.169 17.415,1.387
  rectangle: 6.565,-2.22 7.795,1.387
  lines w0.127: 2.911,-0.137 4.181,-0.137 ; 3.673,-0.772 3.673,0.498 ; 4.41,-2.169 4.41,1.438 9.947,1.438 9.947,-2.169 4.41,-2.169 ; 13.957,-2.169 13.957,1.387 19.494,1.387 19.494,-2.169 13.957,-2.169
Mechanical 1:
  lines w0.127: -38.826,-62.223 -38.826,-19.563 ; -6.106,-40.513 35.894,-40.513 ; 35.894,-40.523 -6.106,-40.523 -6.106,2.137 35.894,2.137 ; 35.894,-40.523 35.894,-20.275 25.805,-20.275 25.805,-11.205 35.894,-11.205 35.894,2.137 ; 35.894,-40.523 35.894,2.137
